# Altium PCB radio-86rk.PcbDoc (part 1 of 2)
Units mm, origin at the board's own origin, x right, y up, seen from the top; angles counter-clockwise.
Board outline 258 x 185 mm, 2 copper layers (Top Layer, Top, Bottom Layer, Bottom); 104 components, 185 nets, 870 pads, 319 vias.
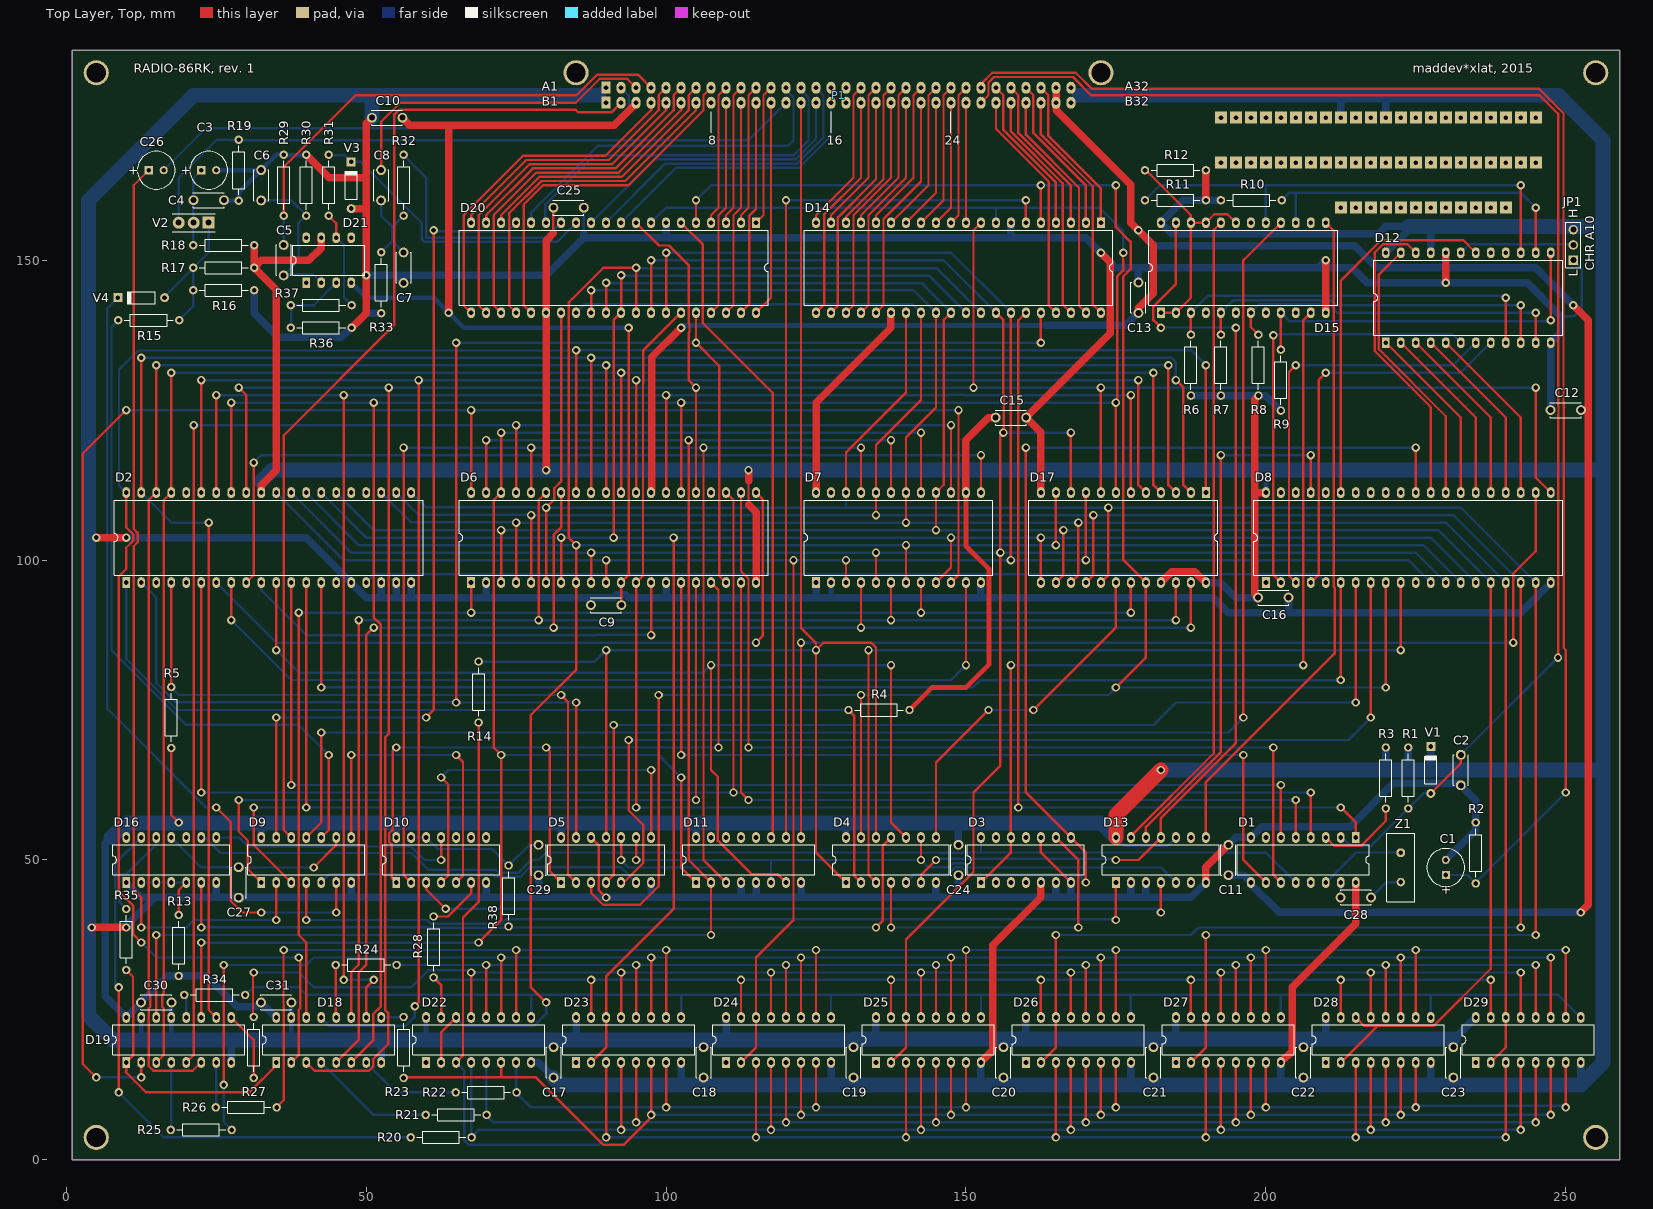
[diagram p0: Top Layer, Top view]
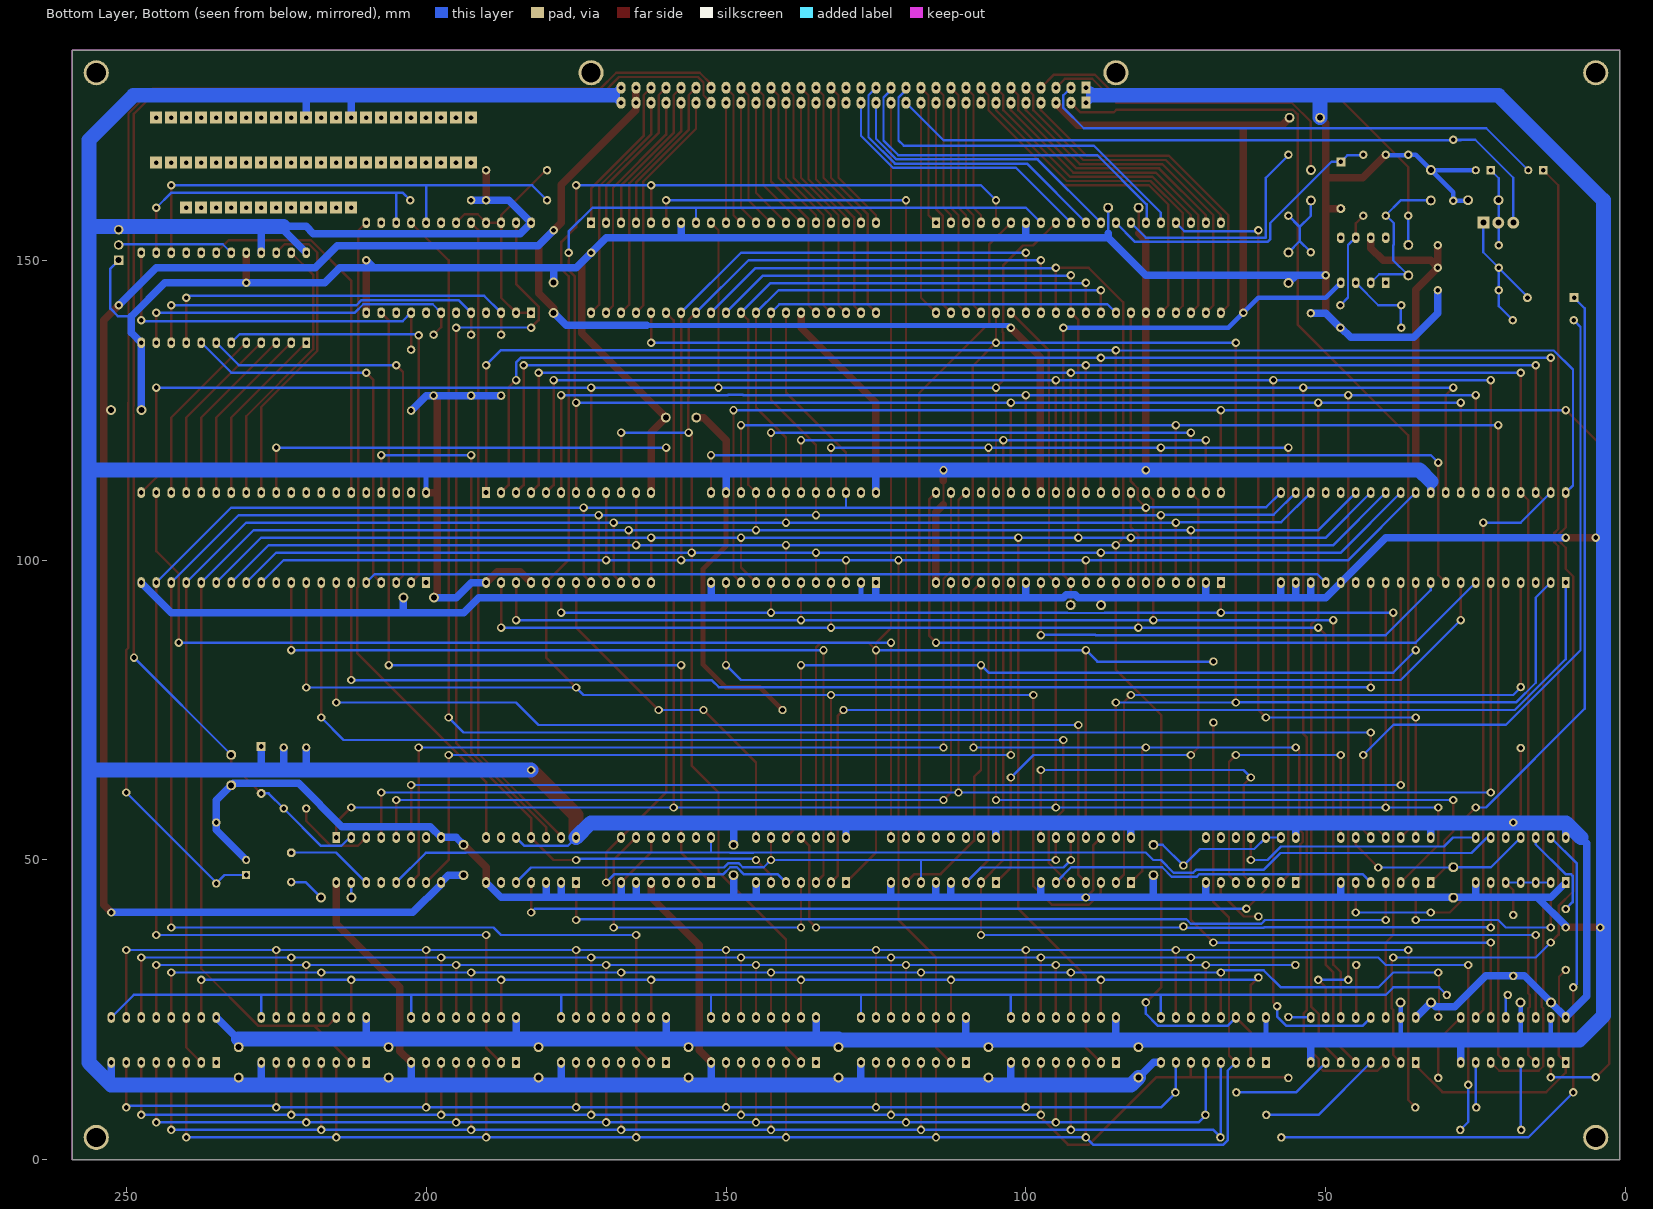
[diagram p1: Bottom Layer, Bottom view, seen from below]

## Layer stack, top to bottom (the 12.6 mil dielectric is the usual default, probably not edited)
Top Solder, Top Mask: solder mask 0.0102, Solder Resist, Dk 3.5
Top Layer, Top: signal copper 0.0356
Dielectric 1: dielectric 0.32, FR-4, Dk 4.8
Bottom Layer, Bottom: signal copper 0.0356
Bottom Solder, Bot Mask: solder mask 0.0102, Solder Resist, Dk 3.5

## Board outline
1,0 1,185 259,185 259,0

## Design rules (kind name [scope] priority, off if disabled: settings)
AssemblyTestPointUsage [All] p1 off:
AssemblyTestpoint [All] p1 off: testpointundercomponent=TRUE minsize=1.016 maxsize=2.54 preferedsize=1.524 minholesize=0 maxholesize=1.016 preferedholesize=0.813 testpointgrid=0.025 usegrid=TRUE gridtolerance=0 allowsidetop=TRUE allowsidebottom=TRUE
Clearance "PCB edge to copper" [OnLayer('Keep-Out Layer, Board') vs OnCopper] p1: gap=0.5
Clearance "Hole to copper" [InPadClass('Hole')] p2: gap=0.4
Clearance "VDD to free pad" [InNet('VDD') AND IsPad AND (Component = 'P1')] p3: gap=0.3
Clearance VDD [InNet('VDD')] p4: gap=0.5
Clearance [All] p5: gap=0.3
ComponentClearance ComponentClearance_1 [NAME LIKE 'C*'] p1: gap=0 collisioncheckmode=3 verticalgap=0.254 showdistances=FALSE
ComponentClearance [All] p2: gap=0.254 collisioncheckmode=3 verticalgap=0.254 showdistances=FALSE
FabricationTestPointUsage [All] p1 off: valid=0 allowmultiple=FALSE
FabricationTestpoint [All] p1 off: side=3 testpointundercomponent=TRUE minsize=1.016 maxsize=2.54 preferedsize=1.524 minholesize=0 maxholesize=1.016 preferedholesize=0.813 testpointgrid=0.025 allowsidetop=TRUE allowsidebottom=TRUE usegrid=TRUE gridtolerance=0
HoleSize [All] p1: absolutevalues=TRUE maxlimit=3.5 minlimit=0.4 maxpercent=80.000 minpercent=20.000
MinimumAnnularRing [All] p1: minimumring=0.25
PlaneClearance [All] p1: clearance=0.254
PolygonConnect PolygonConnect_2 [IsPolygon And InNet('NET 178') And OnLayer('Bottom Layer, Bottom') vs IsVia] p1: connectstyle=Direct reliefconductorwidth=0.33 reliefentries=4 polygonreliefangle="90 Angle" airgapwidth=0.254
PolygonConnect PolygonConnect_1 [IsPolygon And InNet('NET 178') And OnLayer('Bottom Layer, Bottom') vs IsPad] p2: connectstyle=Direct reliefconductorwidth=0.33 reliefentries=4 polygonreliefangle="90 Angle" airgapwidth=0.254
PolygonConnect [All] p3: connectstyle=Relief reliefconductorwidth=0.254 reliefentries=4 polygonreliefangle="90 Angle" airgapwidth=0.254
RoutingVias [All] p1: holewidth=0.8 width=1.4 viastyle="Through Hole" minholewidth=0.8 minwidth=1.4 maxholewidth=0.8 maxwidth=1.4
SilkToSolderMaskClearance "Text over via" [IsVia vs IsText] p1: minsilkscreentomaskgap=0.205 clearancetoexposedcopper=TRUE
SilkToSolderMaskClearance [IsPad] p2: minsilkscreentomaskgap=0.205 clearancetoexposedcopper=TRUE
SolderMaskExpansion [All] p1: expansion=0.11
Width [All] p1: maxlimit=3 minlimit=0.4 preferedwidth=0.4 minimp=50.000000 maximp=50.000000 favimp=50.000000
21 further rules are at their usual default settings.

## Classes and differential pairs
pad class Hole: Free-hole
component class radio-86rk_cpu_pio: C1 C2 C5 C6 C7 C8 C9 C10 C11 C12 C13 C15 C16 C17 C18 C19 C20 C21 C22 C23 C24 C25 C26 C28 C30 C31 D1 D6 D9 D14 D20 D21 P1 R1 R2 R3 R29 R30 R31 R32 R33 R36 R37 V1 V3 Z1
component class radio-86rk_control: C27 C29 D10 D11 D13 D16 D18 D19 R13 R14 R20 R21 R22 R23 R24 R25 R26 R27 R28 R34 R35 R38
component class radio-86rk_dma_crt: C3 C4 D2 D3 D4 D5 D7 D8 D12 D15 JP1 R4 R5 R6 R7 R8 R9 R10 R11 R12 R15 R16 R17 R18 R19 V2 V4
component class radio-86rk_rom_ram: D17 D22 D23 D24 D25 D26 D27 D28 D29

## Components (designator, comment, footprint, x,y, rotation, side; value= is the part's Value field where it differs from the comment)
C1 "4.7uF/6V" CAPPR2.5-6.3x11 230,48.75 r90 top
C2 "0.47 uF" CAPR5.08-5.1x2.5 232.5,65 r90 top
C3 "47uF/15V" CAPPR2.5-6.3x11 23.75,165 r0 top
C4 "0.1uF" CAPR5.08-5.1x2.5 23.75,160 r180 top
C5 "0.22uF" CAPR5.08-5.1x2.5 36.25,150 r90 top
C6 "2200pF" CAPR5.08-5.1x2.5 32.5,162.5 r270 top
C7 "0.1uF" CAPR5.08-5.1x2.5 56.25,148.75 r90 top
C8 "0.1uF" CAPR5.08-5.1x2.5 52.5,162.5 r270 top
C9 "0.1uF" CAPR5.08-5.1x2.5 90,92.5 r0 top
C10 "0.1uF" CAPR5.08-5.1x2.5 53.5,173.75 r0 top
C11 "0.1uF" CAPR5.08-5.1x2.5 193.75,50 r270 top
C12 "0.1uF" CAPR5.08-5.1x2.5 250,125 r0 top
C13 "0.1uF" CAPR5.08-5.1x2.5 178.75,143.75 r270 top
C15 "0.1uF" CAPR5.08-5.1x2.5 157.5,123.75 r180 top
C16 "0.1uF" CAPR5.08-5.1x2.5 201.25,93.75 r180 top
C17 "0.1uF" CAPR5.08-5.1x2.5 81.25,16.25 r270 top
C18 "0.1uF" CAPR5.08-5.1x2.5 106.25,16.25 r270 top
C19 "0.1uF" CAPR5.08-5.1x2.5 131.25,16.25 r270 top
C20 "0.1uF" CAPR5.08-5.1x2.5 156.25,16.25 r270 top
C21 "0.1uF" CAPR5.08-5.1x2.5 181.25,16.25 r270 top
C22 "0.1uF" CAPR5.08-5.1x2.5 206.25,16.25 r270 top
C23 "0.1uF" CAPR5.08-5.1x2.5 231.25,16.25 r270 top
C24 "0.1uF" CAPR5.08-5.1x2.5 148.75,50 r90 top
C25 "0.1uF" CAPR5.08-5.1x2.5 83.75,158.75 r180 top
C26 "10uF/6.3V" CAPPR2.5-6.3x11 15,165 r0 top
C27 "2200pF" CAPR5.08-5.1x2.5 28.75,46.25 r270 top
C28 "*" CAPR5.08-5.1x2.5 215,43.75 r0 top
C29 "300pF" CAPR5.08-5.1x2.5 78.75,50 r270 top
C30 "0.1uF" CAPR5.08-5.1x2.5 15,26.25 r180 top
C31 "0.1uF" CAPR5.08-5.1x2.5 35,26.25 r180 top
D1 "КР580ГФ24" DIP16M 206.25,50 r180 top
D2 "КР580ИК57" DIP40M 33.75,103.75 r0 top
D3 "К155ИЕ4" DIP14M 160,50 r0 top
D4 "К155ЛИ1" DIP14M 137.5,50 r0 top
D5 "К155ЛП5" DIP14M 90,50 r0 top
D6 "КР580ВМ80А" DIP40M 91.25,103.75 r0 top
D7 "КР589ИР12" DIP24M 138.75,103.75 r0 top
D8 "КР580ВГ75" DIP40M 223.75,103.75 r0 top
D9 "К155ЛН1" DIP14M 40,50 r0 top
D10 "К155ЛА3" DIP14M 62.5,50 r0 top
D11 "К155ИД7" DIP16M 113.75,50 r0 top
D12 "К573РФ2" DIP24M 233.75,143.75 r0 top
D13 "К155ТМ2" DIP14M 182.5,50 r0 top
D14 "КР580ИК55" DIP40M 148.75,148.75 r180 top
D15 "К155ИР13" DIP24M 196.25,148.75 r0 top
D16 "К155ИР1" DIP14M 17.5,50 r0 top
D17 "К573РФ2" DIP24M 176.25,103.75 r180 top
D18 "К555КП11" DIP16M 43.75,20 r0 top
D19 "К555КП11" DIP16M 18.75,20 r0 top
D20 "КР580ИК55" DIP40M 91.25,148.75 r180 top
D21 "К140УД608" DIP8M 43.75,150 r0 top
D22 "КР565РУ5" DIP16M 68.75,20 r0 top
D23 "КР565РУ5" DIP16M 93.75,20 r0 top
D24 "КР565РУ5" DIP16M 118.75,20 r0 top
D25 "КР565РУ5" DIP16M 143.75,20 r0 top
D26 "КР565РУ5" DIP16M 168.75,20 r0 top
D27 "КР565РУ5" DIP16M 193.75,20 r0 top
D28 "КР565РУ5" DIP16M 218.75,20 r0 top
D29 "КР565РУ5" DIP16M 243.75,20 r0 top
JP1 "PLS-3" HDR1X3 251.25,150 r90 top
P1 "СНП58-64/94x9В-23-2-В" snp58 90,178.75 r0 top
R1 "2K" AXIAL-0.4 223.75,63.67 r90 top
R2 "10K" AXIAL-0.4 235,51.17 r270 top
R3 "1K" AXIAL-0.4 220,63.67 r270 top
R4 "10K" AXIAL-0.4 135.5,75 r180 top
R5 "10K" AXIAL-0.4 17.5,73.75 r90 top
R6 "10K" AXIAL-0.4 187.5,132.5 r270 top
R7 "10K" AXIAL-0.4 192.5,132.5 r270 top
R8 "10K" AXIAL-0.4 198.75,132.5 r270 top
R9 "10K" AXIAL-0.4 202.5,130 r270 top
R10 "10K" AXIAL-0.4 197.58,160 r180 top
R11 "10K" AXIAL-0.4 184.92,160 r0 top
R12 "20K" AXIAL-0.4 184.92,165 r0 top
R13 "20K" AXIAL-0.4 18.75,35.75 r90 top
R14 "33" AXIAL-0.4 68.75,78 r90 top
R15 "2.2k" AXIAL-0.4 13.75,140 r0 top
R16 "1k" AXIAL-0.4 26.25,145 r180 top
R17 "2.2k" AXIAL-0.4 26.25,148.75 r0 top
R18 "56" AXIAL-0.4 26.25,152.5 r180 top
R19 "75" AXIAL-0.4 28.75,165 r90 top
R20 "33" AXIAL-0.4 62.5,3.75 r180 top
R21 "33" AXIAL-0.4 65,7.5 r180 top
R22 "33" AXIAL-0.4 70,11.25 r180 top
R23 "33" AXIAL-0.4 56.25,18.75 r90 top
R24 "33" AXIAL-0.4 50,32.5 r180 top
R25 "33" AXIAL-0.4 22.5,5 r180 top
R26 "33" AXIAL-0.4 30,8.75 r180 top
R27 "33" AXIAL-0.4 31.25,18.75 r270 top
R28 "33" AXIAL-0.4 61.25,35.5 r90 top
R29 "12K" AXIAL-0.4 36.25,162.5 r270 top
R30 "2.4K" AXIAL-0.4 40,162.5 r270 top
R31 "330" AXIAL-0.4 43.75,162.5 r90 top
R32 "1K" AXIAL-0.4 56.25,162.5 r270 top
R33 "1K" AXIAL-0.4 52.5,146.25 r90 top
R34 "33" AXIAL-0.4 24.75,27.5 r180 top
R35 "*" AXIAL-0.4 10,36.75 r90 top
R36 "1K" AXIAL-0.4 42.5,138.75 r0 top
R37 "7.5K" AXIAL-0.4 42.5,142.5 r180 top
R38 "430" AXIAL-0.4 73.75,44 r90 top
V1 "KD503A" DO-35A 227.5,65 r90 top
V2 "KT315" KT315 21.25,156.25 r180 top
V3 "KD503A" DO-35A 47.5,162.5 r90 top
V4 "KD503A" DO-35A 12.5,143.75 r180 top
Z1 "16 MHz" HC-49U 222.5,48.75 r270 top

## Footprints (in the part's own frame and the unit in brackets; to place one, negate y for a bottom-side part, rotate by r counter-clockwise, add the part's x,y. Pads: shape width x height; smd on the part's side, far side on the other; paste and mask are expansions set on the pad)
AXIAL-0.4 [mm] "Axial Device, Thru-Hole; 2 Leads; 0.4 in Pin Spacing"
  round 1.4 hole 0.8: 1(-5.08,0) 2(5.08,0)
  silkscreen extent -4.06,-1.02 4.06,1.02
CAPPR2.5-6.3x11 [mm] "Capacitor, Electrolytic, Radial; Body 6.3 x 11 mm (Dia.xH typ); Pin Spacing 2.5 mm (typ)"
  rect 1.35x1.35 hole 0.8: 1(-1.25,0)
  round 1.35 hole 0.8: 2(1.25,0)
  silkscreen extent -3.15,-3.15 3.15,3.15
CAPR5.08-5.1x2.5 [mm] "Capacitor, Ceramic, Thru-Hole, Dipped Radial; Body 5.1 x 2.5 mm (WxT) Pin Spacing 5.08 mm (typ)"
  round 1.65 hole 1: 1(-2.54,0) 2(2.54,0)
  silkscreen extent -2.55,-1.25 2.55,1.25
DIP8M [mm] "2.5mm grid"
  rect 1.3x1.8 hole 0.8: 1(-3.75,-3.75)
  rrect100% 1.3x1.8 hole 0.8: 2(-1.25,-3.75) 3(1.25,-3.75) 4(3.75,-3.75) 5(3.75,3.75) 6(1.25,3.75) 7(-1.25,3.75) 8(-3.75,3.75)
  silkscreen extent -6,-2.5 6,2.5
DIP14M [mm] "2.5mm grid"
  rect 1.3x1.8 hole 0.8: 1(-7.5,-3.75)
  rrect100% 1.3x1.8 hole 0.8: 2(-5,-3.75) 3(-2.5,-3.75) 4(0,-3.75) 5(2.5,-3.75) 6(5,-3.75) 7(7.5,-3.75) 8(7.5,3.75) 9(5,3.75) 10(2.5,3.75) 11(0,3.75) 12(-2.5,3.75) 13(-5,3.75) 14(-7.5,3.75)
  silkscreen extent -9.75,-2.5 9.75,2.5
DIP16M [mm] "2.5mm grid"
  rect 1.3x1.8 hole 0.8: 1(-8.75,-3.75)
  rrect100% 1.3x1.8 hole 0.8: 2(-6.25,-3.75) 3(-3.75,-3.75) 4(-1.25,-3.75) 5(1.25,-3.75) 6(3.75,-3.75) 7(6.25,-3.75) 8(8.75,-3.75) 9(8.75,3.75) 10(6.25,3.75) 11(3.75,3.75) 12(1.25,3.75) 13(-1.25,3.75) 14(-3.75,3.75) 15(-6.25,3.75) 16(-8.75,3.75)
  silkscreen extent -11,-2.5 11,2.5
DIP24M [mm] "2.5mm grid, 239.24-1, 239.24-2, 239.24-6, 239.24-7"
  rect 1.3x1.8 hole 0.8: 1(-13.75,-7.5)
  rrect100% 1.3x1.8 hole 0.8: 2(-11.25,-7.5) 3(-8.75,-7.5) 4(-6.25,-7.5) 5(-3.75,-7.5) 6(-1.25,-7.5) 7(1.25,-7.5) 8(3.75,-7.5) 9(6.25,-7.5) 10(8.75,-7.5) 11(11.25,-7.5) 12(13.75,-7.5) 13(13.75,7.5) 14(11.25,7.5) 15(8.75,7.5) 16(6.25,7.5) 17(3.75,7.5) 18(1.25,7.5) 19(-1.25,7.5) 20(-3.75,7.5) 21(-6.25,7.5) 22(-8.75,7.5) 23(-11.25,7.5) 24(-13.75,7.5)
  silkscreen extent -15.75,-6.25 15.75,6.25
DIP40M [mm] "2.5mm grid, 2123.40-1"
  rect 1.3x1.8 hole 0.8: 1(-23.75,-7.5)
  rrect100% 1.3x1.8 hole 0.8: 2(-21.25,-7.5) 3(-18.75,-7.5) 4(-16.25,-7.5) 5(-13.75,-7.5) 6(-11.25,-7.5) 7(-8.75,-7.5) 8(-6.25,-7.5) 9(-3.75,-7.5) 10(-1.25,-7.5) 11(1.25,-7.5) 12(3.75,-7.5) 13(6.25,-7.5) 14(8.75,-7.5) 15(11.25,-7.5) 16(13.75,-7.5) 17(16.25,-7.5) 18(18.75,-7.5) 19(21.25,-7.5) 20(23.75,-7.5) 21(23.75,7.5) 22(21.25,7.5) 23(18.75,7.5) 24(16.25,7.5) 25(13.75,7.5) 26(11.25,7.5) 27(8.75,7.5) 28(6.25,7.5) 29(3.75,7.5) 30(1.25,7.5) 31(-1.25,7.5) 32(-3.75,7.5) 33(-6.25,7.5) 34(-8.75,7.5) 35(-11.25,7.5) 36(-13.75,7.5) 37(-16.25,7.5) 38(-18.75,7.5) 39(-21.25,7.5) 40(-23.75,7.5)
  silkscreen extent -25.75,-6.25 25.75,6.25
DO-35A [mm] "Diode, Axial; Body 4.6 x 1.9 mm (LxDia. max), Lead Dia. 0.53 mm (max)"
  round 1.5 hole 0.8: 1(-3.9,0)
  rect 1.5x1.5 hole 0.8: 2(3.9,0)
  silkscreen extent -2.3,-1 2.4,1
HC-49U [mm] "Quartz Crystal, Thru-Hole; 2 Leads; Body 11.35 x 4.65 x 13.46 mm (LxWxH max)"
  oct 1.4x1.4 hole 0.8: 1(-2.44,0)
  round 1.4 hole 0.8: 2(2.44,0)
  silkscreen extent -5.7,-2.35 5.7,2.35
HDR1X3 [mm] "Connector; Header; 3 Position"
  rect 1.6x1.6 hole 1: 1(0,0)
  round 1.6 hole 1: 2(2.54,0) 3(5.08,0)
  silkscreen extent -1.27,-1.27 6.35,1.27
KT315 [mm]
  rect 2x2 hole 1: B(-2.5,0)
  round 2 hole 1: C(0,0) E(2.5,0)
  silkscreen extent -3.6,-1.5 3.6,1.5
snp58 [mm]
  rect 1.5x2 hole 0.8: A1(0,0) B1(0,-2.5)
  oval 1.5x2 hole 0.8: A2(2.5,0) A3(5,0) A4(7.5,0) A5(10,0) A6(12.5,0) A7(15,0) A8(17.5,0) A9(20,0) A10(22.5,0) A11(25,0) A12(27.5,0) A13(30,0) A14(32.5,0) A15(35,0) A16(37.5,0) A17(40,0) A18(42.5,0) A19(45,0) A20(47.5,0) A21(50,0) A22(52.5,0) A23(55,0) A24(57.5,0) A25(60,0) A26(62.5,0) A27(65,0) A28(67.5,0) A29(70,0) A30(72.5,0) A31(75,0) A32(77.5,0) B2(2.5,-2.5) B3(5,-2.5) B4(7.5,-2.5) B5(10,-2.5) B6(12.5,-2.5) B7(15,-2.5) B8(17.5,-2.5) B9(20,-2.5) B10(22.5,-2.5) B11(25,-2.5) B12(27.5,-2.5) B13(30,-2.5) B14(32.5,-2.5) B15(35,-2.5) B16(37.5,-2.5) B17(40,-2.5) B18(42.5,-2.5) B19(45,-2.5) B20(47.5,-2.5) B21(50,-2.5) B22(52.5,-2.5) B23(55,-2.5) B24(57.5,-2.5) B25(60,-2.5) B26(62.5,-2.5) B27(65,-2.5) B28(67.5,-2.5) B29(70,-2.5) B30(72.5,-2.5) B31(75,-2.5) B32(77.5,-2.5)

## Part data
C1 C3 C26: library part "Cap Pol2", "Polarized Capacitor (Axial)"
C2 C4 C5 C6 C7 C8 C9 C10 C11 C12 C13 C15 C16 C17 C18 C19 C20 C21 C22 C23 C24 C25 C27 C28 C29 C30 C31: library part Cap, "Capacitor"
D1: "Clock generator and driver for 8080A CPU"
D2: "Programmable DMA controller"
D3: library part SN7492AN, "Divide-by-Twelve Counter"
D4: library part SN7408N, "Quadruple 2-Input Positive-AND Gate"
D5: library part SN7486N, "Quadruple 2-Input Exclusive-OR Gate"
D6: "8-bit N-channel microprocessor"
D7: library part 8212, "8-bit input/output port"
D8: "Programmable CRT controller"
D9: library part SN7404N, "Hex Inverter"
D10: library part SN7400N, "Quadruple 2-Input Positive-NAND Gate"
D11: library part SN74LS138N, "3-Line to 8-Line Decoder / Demultiplexer"
D13: library part SN7474N, "Dual D-Type Positive-Edge-Triggered Flip-Flop with Preset and Clear"
D14 D20: "Programmable peripheral interface"
D15: library part SN74198N, "8-Bit Shift Register"
D16: library part SN7495AN, "4-Bit Parallel-Access Shift Register"
D18 D19: library part SN74LS257BN, "Quadruple 2-Line to 1-Line Data Selector/Multiplexer with 3-State Outputs"
D21: library part MC1456P1, "High-Performance Operational Amplifier"
D22 D23 D24 D25 D26 D27 D28 D29: library part 4164, "64K X 1 bit dynamic RAM"
JP1: library part "Header 3", "Header, 3-Pin"
R1 R2 R3 R4 R5 R6 R7 R8 R9 R10 R11 R12 R13 R14 R15 R16 R17 R18 R19 R20 R21 R22 R23 R24 R25 R26 R27 R28 R29 R30 R31 R32 R33 R34 R35 R36 R37 R38: library part Res2, "Resistor"
V1 V3 V4: library part "Diode 1N4149", "Computer Diode"
V2: library part NPN, "NPN Bipolar Transistor"
Z1: library part XTAL, "Crystal Oscillator"

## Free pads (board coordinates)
  rect 2x2 hole 0.8: 0(192.5,166.25) 0(192.5,173.75) 0(195,166.25) 0(195,173.75) 0(197.5,166.25) 0(197.5,173.75) 0(200,166.25) 0(200,173.75) 0(202.5,166.25) 0(202.5,173.75) 0(205,166.25) 0(205,173.75) 0(207.5,166.25) 0(207.5,173.75) 0(210,166.25) 0(210,173.75) 0(212.5,158.75) 0(212.5,166.25) 0(212.5,173.75) 0(215,158.75) 0(215,166.25) 0(215,173.75) 0(217.5,158.75) 0(217.5,166.25) 0(217.5,173.75) 0(220,158.75) 0(220,166.25) 0(220,173.75) 0(222.5,158.75) 0(222.5,166.25) 0(222.5,173.75) 0(225,158.75) 0(225,166.25) 0(225,173.75) 0(227.5,158.75) 0(227.5,166.25) 0(227.5,173.75) 0(230,158.75) 0(230,166.25) 0(230,173.75) 0(232.5,158.75) 0(232.5,166.25) 0(232.5,173.75) 0(235,158.75) 0(235,166.25) 0(235,173.75) 0(237.5,158.75) 0(237.5,166.25) 0(237.5,173.75) 0(240,158.75) 0(240,166.25) 0(240,173.75) 0(242.5,166.25) 0(242.5,173.75) 0(245,166.25) 0(245,173.75)
  round 4.2 hole 3.2: hole(5,181.25) hole(5,3.75) hole(85,181.25) hole(172.5,181.25) hole(255,181.25) hole(255,3.75)

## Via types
v1: diameter 1.4, hole 0.8, Top Layer, Top to Bottom Layer, Bottom, 318 vias
v2: diameter 1.4, hole 0.8, Top Layer, Top to Bottom Layer, Bottom, tented both sides, 1 vias

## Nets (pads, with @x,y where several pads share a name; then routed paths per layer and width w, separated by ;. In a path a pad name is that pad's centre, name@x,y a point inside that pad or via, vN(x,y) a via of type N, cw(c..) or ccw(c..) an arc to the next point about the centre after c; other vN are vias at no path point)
A0: D2.32 D6.25 D8.21 D14.9 D17.8 D18.3 D20.9 | length 475.2
  Top Layer, Top w0.4: v1(28.75,128.75) 30,127.5 D2.32@30,111.25 ; D18.3@40,16.25 41.4,14.85 50.476,14.85 51.15,15.524 51.15,16.776 53.65,19.276 53.65,24.476 53.15,24.976 53.15,70.4 53.75,71 v1(53.75,128.75) ; D20.9@95,156.25 98.8,152.45 100.497,152.45 103.75,149.197 103.75,139.48 103.9,139.33 103.9,138.02 103.8,137.92 103.8,129.95 v1(105,128.75) D6.25@105,111.25 ; v1(151.25,128.75) 151.25,155 D14.9@152.5,156.25 ; D17.8@172.5,111.25 v1(172.5,128.75) ; v1(245,128.75) 245,113.75 D8.21@247.5,111.25
  Bottom Layer, Bottom w0.4: v1(28.75,128.75) v1(53.75,128.75) ; v1@53.75,128.7 v1@104.95,128.7 ; v1(105,128.75) v1(151.25,128.75) v1(172.5,128.75) v1(245,128.75)
A1: D2.33 D6.26 D14.8 D17.7 D18.6 D20.8 | length 418
  Top Layer, Top w0.4: D2.33@27.5,111.25 v1(27.5,126.25) ; D18.6@47.5,16.25 51.15,19.9 51.15,24.276 52.45,25.576 52.45,89.247 51.25,90.447 v1(51.25,126.25) ; D6.26@102.5,111.25 v1(102.5,126.25) ; D17.7@175,111.25 v1(175,126.25) 175.2,126.45 175.2,147.253 176.2,148.253 176.2,149.975 176.175,150 176.175,151.175 v1(176.25,151.25)
  Bottom Layer, Bottom w0.4: v1(27.5,126.25) 27.55,126.2 v1@51.2,126.2 ; v1(51.25,126.25) v1(102.5,126.25) v1(175,126.25) ; D20.8@97.5,156.25 100,158.75 172.257,158.75 176.25,154.757 v1(176.25,151.25) ; D14.8@155,156.25 155,158.749
A2: D2.34 D6.27 D17.6 D18.10 | length 310.6
  Top Layer, Top w0.4: D2.34@25,111.25 v1(25,127.5) ; v1(46.25,30) 46.25,98.125 v1(46.25,127.5) ; D18.10@50,23.75 50,28.75 v1(51.25,30) ; D6.27@100,111.25 100,112.5 v1(100,127.5) ; D17.6@177.5,111.25 v1(177.5,127.5)
  Bottom Layer, Bottom w0.4: v1(25,127.5) v1(46.25,127.5) v1(100,127.5) 147.133,127.5 147.207,127.574 149.662,127.574 149.736,127.5 v1(177.5,127.5) ; v1(46.25,30) v1(51.25,30)
A3: D2.35 D6.29 D17.5 D18.13 | length 336.2
  Top Layer, Top w0.4: D2.35@22.5,111.25 v1(22.5,130) ; v1(58.125,25.625) 58.75,26.25 v1(58.75,130) ; D6.29@95,111.25 v1(95,130) ; v1(178.75,130) 178.75,112.5 D17.5@180,111.25
  Bottom Layer, Bottom w0.4: v1(22.5,130) v1(58.75,130) v1(95,130) v1(178.75,130) ; D18.13@42.5,23.75 43.9,22.35 56.547,22.35 58.125,23.928 v1(58.125,25.625)
A4: D2.37 D6.30 D17.4 D19.3 | length 320.5
  Top Layer, Top w0.4: D19.3@15,16.25 16.25,17.5 16.25,25.25 16,25.5 16,27.5 16.25,27.75 16.25,110 D2.37@17.5,111.25 v1(17.5,131.25) ; D6.30@92.5,111.25 v1(92.5,131.25) ; v1(181.25,131.25) 181.25,112.5 D17.4@182.5,111.25
  Bottom Layer, Bottom w0.4: v1(17.5,131.25) v1(92.5,131.25) v1(181.25,131.25)
A5: D2.38 D6.31 D17.3 D19.6 | length 339
  Top Layer, Top w0.4: v1(15,132.5) D2.38@15,111.25 13.75,110 13.75,27.75 14,27.5 14,25.5 13.75,25.25 13.75,15.624 14.524,14.85 21.1,14.85 D19.6@22.5,16.25 ; D6.31@90,111.25 v1(90,132.5) ; v1(183.75,132.5) 183.75,112.5 D17.3@185,111.25
  Bottom Layer, Bottom w0.4: v1(15,132.5) v1(90,132.5) v1(183.75,132.5)
A6: D2.39 D6.32 D17.2 D19.10 | length 336.9
  Top Layer, Top w0.4: D2.39@12.5,111.25 v1(12.5,133.75) ; v1(23.75,106.25) 23.75,25 D19.10@25,23.75 ; D6.32@87.5,111.25 v1(87.5,133.75) ; v1(185,130) 186.25,128.75 186.25,112.5 D17.2@187.5,111.25
  Bottom Layer, Bottom w0.4: D2.39@12.5,111.25 17.5,106.25 v1(23.75,106.25) ; v1(12.5,133.75) v1(87.5,133.75) 184.197,133.75 185,132.947 v1(185,130)
A7: D2.40 D6.33 D17.1 D18.2 | length 373.2
  Top Layer, Top w0.4: D2.40@10,111.25 10,105.447 11.2,104.247 11.2,103.253 10,102.053 10,98.507 8.75,97.257 8.75,44.777 11.2,42.327 11.2,37.55 v1(12.5,36.25) ; D18.2@37.5,16.25 38.75,17.5 38.75,25 39,25.25 39,33.5 v1(38.75,33.75) ; D6.33@85,111.25 v1(85,135) ; D17.1@190,111.25 v1(190,132.5)
  Bottom Layer, Bottom w0.4: D2.40@10,111.25 8.8,112.45 8.8,131.747 12.003,134.95 84.95,134.95 v1(85,135) 187.5,135 v1(190,132.5) ; v1(12.5,36.25) 15,33.75 v1(38.75,33.75)
A8: D6.34 D7.4 D17.23 D18.5 | length 249.4
  Top Layer, Top w0.4: D18.5@45,16.25 48.75,20 48.75,31.25 50,32.5 50,87.5 v1(51.25,88.75) ; v1(81.25,88.75) 81.3,88.8 81.3,104.247 82.5,105.447 D6.34@82.5,111.25 ; v1(132.5,88.75) D7.4@132.5,96.25 ; v1(187.5,88.75) D17.23@187.5,96.25
  Bottom Layer, Bottom w0.4: v1(51.25,88.75) v1(81.25,88.75) v1(132.5,88.75) v1(187.5,88.75)
A9: D6.35 D7.6 D17.22 D18.11 | length 237.3
  Top Layer, Top w0.4: D18.11@47.5,23.75 47.5,31.273 48.75,32.523 v1(48.75,90) ; v1(78.75,90) 78.8,90.05 78.8,110.05 D6.35@80,111.25 ; v1(137.5,90) D7.6@137.5,96.25 ; v1(185,90) D17.22@185,96.25
  Bottom Layer, Bottom w0.4: v1(48.75,90) v1(78.75,90) v1(137.5,90) v1(185,90)
A10: D6.1 D7.8 D17.19 D18.14 | length 221.8
  Top Layer, Top w0.4: v1(38.75,91.25) 38.75,37.5 40,36.25 D18.14@40,23.75 ; v1(67.5,91.25) D6.1@67.5,96.25 ; v1(142.5,91.25) D7.8@142.5,96.25 ; v1(177.5,91.25) D17.19@177.5,96.25
  Bottom Layer, Bottom w0.4: v1(38.75,91.25) v1(67.5,91.25) 86.836,91.25 86.911,91.175 93.089,91.175 93.164,91.25 v1(142.5,91.25) v1(177.5,91.25)
A11: D6.40 D7.10 D19.2 | length 307
  Top Layer, Top w0.4: v1(5,13.75) 2.75,16 2.75,117.75 v1(10,125) ; v1(12.5,13.75) D19.2@12.5,16.25 ; D6.40@67.5,111.25 v2(67.5,125) ; D7.10@147.5,96.25 148.75,97.5 v1(148.75,125)
  Bottom Layer, Bottom w0.4: v1(5,13.75) v1(12.5,13.75) ; v1(10,125) v2(67.5,125) v1(148.75,125)
A12: D6.37 D7.15 D19.5 | length 255.5
  Top Layer, Top w0.4: D19.5@20,16.25 21.25,17.5 v1(21.25,122.5) ; D6.37@75,111.25 v1(75,122.5) ; D7.15@147.5,111.25 v1(147.5,122.5)
  Bottom Layer, Bottom w0.4: v1(21.25,122.5) v1(75,122.5) v1(147.5,122.5)
A13: D6.38 D7.17 D11.1 D19.11 | length 276.2
  Top Layer, Top w0.4: D19.11@22.5,23.75 v1(22.5,36.25) ; v1(68.75,36.25) 72.5,40 v1(72.5,67.5) 71.3,68.7 71.3,110.05 D6.38@72.5,111.25 v1(72.5,121.25) ; v1(102.5,63.75) 102.5,48.75 D11.1@105,46.25 ; D7.17@142.5,111.25 v1(142.5,121.25)
  Bottom Layer, Bottom w0.4: v1@22.7,36.2 37.972,36.2 37.999,36.174 68.674,36.174 v1(68.75,36.25) ; v1(72.5,67.5) 98.75,67.5 v1(102.5,63.75) ; v1(72.5,121.25) v1(142.5,121.25)
A14: D6.39 D7.19 D11.2 D19.14 | length 275.3
  Top Layer, Top w0.4: D19.14@15,23.75 v1(15,37.5) ; D6.39@70,111.25 v1(70,120) ; v1(103.75,120) 103.75,95 103.8,94.95 103.8,49.95 D11.2@107.5,46.25 v1(107.5,37.5) ; D7.19@137.5,111.25 v1(137.5,120)
  Bottom Layer, Bottom w0.4: v1(15,37.5) v1(107.5,37.5) ; v1(70,120) v1(103.75,120) v1(137.5,120)
A15: D5.10 D6.36 D7.21 D10.2 D11.3 | length 261.1
  Top Layer, Top w0.4: v1(56.25,118.75) 56.25,109.375 56.25,47.5 D10.2@57.5,46.25 ; D6.36@77.5,111.25 v1(77.5,118.75) ; v1(92.5,50) D5.10@92.5,53.75 ; v1(106.25,118.75) 106.25,50 D11.3@110,46.25 ; D7.21@132.5,111.25 v1(132.5,118.75)
  Bottom Layer, Bottom w0.4: v1(56.25,118.75) v1(77.5,118.75) v1(106.25,118.75) v1(132.5,118.75) ; v1(92.5,50) 93.75,48.75 107.5,48.75 D11.3@110,46.25
ATAPI: C5.2 P1.A4 R29.2 | length 81.5
  Top Layer, Top w0.4: R29.2@36.25,157.5 36.25,165.527 48.223,177.5 85.068,177.5 88.518,180.95 95.3,180.95 P1.A4@97.5,178.75
  Bottom Layer, Bottom w0.4: C5.2@36.25,152.54 R29.2@36.25,157.5
ATAPO: C8.1 P1.A3 | length 54.1
  Top Layer, Top w0.4: C8.1@52.5,165.04 52.5,173.074 55.676,176.25 84.943,176.25 88.943,180.25 93.5,180.25 P1.A3@95,178.75
B\W\R\: D4.1 D4.12 D5.11 P1.B14 R14.2 | length 263.9
  Top Layer, Top w0.4: D5.11@90,53.75 v1(90,85) ; P1.B14@122.5,176.25 122.5,88.65 125,86.15 v1(125,85) ; D4.1@130,46.25 125,51.25 v1(125,85) ; D4.12@135,53.75 135,85.447 134.247,86.2 126.2,86.2 v1(125,85)
  Bottom Layer, Bottom w0.4: R14.2@68.75,83.08 88.08,83.08 v1(90,85) v1(125,85)
BEEP: D6.16 D9.1 | length 127.8
  Top Layer, Top w0.4: v1(28.75,60) 28.75,54.75 30.25,53.25 30.25,48.5 D9.1@32.5,46.25 ; v1(105,60) D6.16@105,96.25
  Bottom Layer, Bottom w0.4: v1(28.75,60) v1(105,60)
BUZ: C26.2 P1.A2 | length 85.7
  Bottom Layer, Bottom w0.4: C26.2@16.25,165 23.25,172 90.368,172 93.75,175.382 93.75,177.5 P1.A2@92.5,178.75
C\A\S\: D22.15 D23.15 D24.15 D25.15 D26.15 D27.15 D28.15 D29.15 R28.1 | length 227.4
  Top Layer, Top w0.4: R28.1@61.25,30.42 62.5,29.17 D22.15@62.5,23.75 ; D23.15@87.5,23.75 v1(87.5,30) ; D24.15@112.5,23.75 v1(112.5,30) ; D25.15@137.5,23.75 v1(137.5,30) ; D26.15@162.5,23.75 v1(162.5,30) ; D27.15@187.5,23.75 v1(187.5,30) ; D28.15@212.5,23.75 v1(212.5,30) ; D29.15@237.5,23.75 v1(237.5,30)
  Bottom Layer, Bottom w0.4: R28.1@61.25,30.42 61.67,30 v1(87.5,30) v1(112.5,30) v1(137.5,30) v1(162.5,30) v1(187.5,30) v1(212.5,30) v1(237.5,30)
C\S\C\R\T\: D8.22 D11.9 | length 177.8
  Top Layer, Top w0.4: D11.9@122.5,53.75 v1(122.5,86.25) ; v1(241.25,86.25) 241.25,97.75 245,101.5 D8.22@245,111.25
  Bottom Layer, Bottom w0.4: v1(122.5,86.25) v1(241.25,86.25)
C\S\D\M\A\: D2.11 D4.10 D11.7 | length 189.6
  Top Layer, Top w0.4: v1(35,85) D2.11@35,96.25 ; v1(107.5,82.5) 107.5,65.023 108.65,63.873 108.65,53.224 114.224,47.65 118.6,47.65 D11.7@120,46.25 ; v1(137.5,82.5) 137.5,56.25 D4.10@140,53.75
  Bottom Layer, Bottom w0.4: v1(35,85) 38.75,81.25 106.25,81.25 v1(107.5,82.5) v1(137.5,82.5)
C\S\P\P\I\0\: D11.11 D20.6 | length 108.9
  Top Layer, Top w0.4: D20.6@102.5,156.25 106.15,152.6 106.15,139.475 117.775,127.85 117.775,54.025 D11.11@117.5,53.75
C\S\P\P\I\1\: D11.10 D14.6 | length 150
  Top Layer, Top w0.4: D11.10@120,53.75 120,103.75 v1(120,160) ; D14.6@160,156.25 v1(160,160)
  Bottom Layer, Bottom w0.4: v1(120,160) v1(160,160)
C\S\R\O\M\: D4.8 D17.18 | length 59.3
  Top Layer, Top w0.4: D4.8@145,53.75 145,66.25 v1(153.75,75) ; v1(161.25,75) 175,88.75 D17.18@175,96.25
  Bottom Layer, Bottom w0.4: v1(153.75,75) v1(161.25,75)
CHR_A10: D12.19 JP1.2 | length 19.4
  Bottom Layer, Bottom w0.4: D12.19@232.5,151.25 233.9,152.65 251.1,152.65 JP1.2@251.25,152.5
CLK: D1.6 D2.12 | length 207.5
  Top Layer, Top w0.4: v1(37.5,62.5) D2.12@37.5,96.25 ; D1.6@202.5,53.75 v1(202.5,62.5)
  Bottom Layer, Bottom w0.4: v1(37.5,62.5) v1(202.5,62.5)
D0: D2.30 D6.10 D7.3 D8.12 D14.34 D17.9 D20.34 D24.2 D24.14 | length 417.8
  Top Layer, Top w0.4: D6.10@90,96.25 v1(90,100) ; D20.34@100,141.25 v1(100,151.25) ; D24.2@112.5,16.25 115,18.75 D24.14@115,23.75 115,33.75 121.25,40 v1(121.25,100) ; D7.3@130,96.25 v1(130,100) ; v1(157.5,100) D14.34@157.5,141.25 ; v1(170,100) D17.9@170,111.25
  Bottom Layer, Bottom w0.4: D2.30@35,111.25 46.3,99.95 89.95,99.95 v1(90,100) v1(121.25,100) v1(130,100) v1(157.5,100) v1(170,100) 223.75,100 D8.12@227.5,96.25 ; v1(100,151.25) 147.5,151.25 D14.34@157.5,141.25
D1: D2.29 D6.9 D7.5 D8.13 D14.33 D17.10 D20.33 D25.2 D25.14 | length 433.2
  Top Layer, Top w0.4: D6.9@87.5,96.25 v1(87.5,101.25) ; D20.33@97.5,141.25 v1(97.5,150) ; D7.5@135,96.25 v1(135,101.25) ; D25.2@137.5,16.25 140,18.75 D25.14@140,23.75 140,36.75 151.25,48 151.25,61.25 155.75,65.75 v1(155.75,101.25) 155.75,120.75 v1(156.25,121.25) 156.285,121.285 156.285,127.132 156.25,127.167 156.25,140 D14.33@155,141.25 ; D17.10@167.5,111.25 v1(167.5,121.25)
  Bottom Layer, Bottom w0.4: D2.29@37.5,111.25 47.55,101.2 87.45,101.2 v1(87.5,101.25) v1(135,101.25) v1(155.75,101.25) 225,101.25 D8.13@230,96.25 ; v1(97.5,150) 146.25,150 D14.33@155,141.25 ; v1(156.25,121.25) v1(167.5,121.25)
D2: D2.28 D6.8 D7.7 D8.14 D14.32 D17.11 D20.32 D22.2 D22.14 | length 443.7
  Top Layer, Top w0.4: D22.2@62.5,16.25 62.5,21.25 D22.14@65,23.75 ; v1(80,26.25) 77.425,28.825 77.425,74.122 85,81.697 D6.8@85,96.25 v1(85,102.5) 83.8,103.7 83.8,142.997 89.553,148.75 v1(95,148.75) D20.32@95,141.25 ; D7.7@140,96.25 v1(140,102.5) ; v1(165,102.5) D17.11@165,111.25
  Bottom Layer, Bottom w0.4: D2.28@40,111.25 48.8,102.45 84.95,102.45 v1(85,102.5) v1(140,102.5) v1(165,102.5) 226.25,102.5 D8.14@232.5,96.25 ; D22.14@65,23.75 66.4,22.35 77.976,22.35 80,24.374 v1(80,26.25) ; v1(95,148.75) 95.076,148.674 145.076,148.674 D14.32@152.5,141.25
D3: D2.27 D6.7 D7.9 D8.15 D14.31 D17.13 D20.31 D23.2 D23.14 | length 419.8
  Top Layer, Top w0.4: D6.7@82.5,96.25 v1(82.5,103.75) ; D23.2@87.5,16.25 90,18.75 D23.14@90,23.75 90,30.602 101.25,41.852 v1(101.25,103.75) ; v1(91.25,103.75) 91.25,140 D20.31@92.5,141.25 v1(92.5,147.5) ; D7.9@145,96.25 147.5,98.75 v1(147.5,103.75) ; D17.13@162.5,96.25 v1(162.5,103.75)
  Bottom Layer, Bottom w0.4: D2.27@42.5,111.25 50.05,103.7 v1@82.45,103.7 ; v1(82.5,103.75) v1(91.25,103.75) v1(101.25,103.75) v1(147.5,103.75) v1(162.5,103.75) 227.5,103.75 D8.15@235,96.25 ; v1(92.5,147.5) 92.576,147.424 143.826,147.424 D14.31@150,141.25
D4: D2.26 D6.3 D7.16 D8.16 D14.30 D17.14 D20.30 D28.2 D28.14 | length 418.6
  Top Layer, Top w0.4: D6.3@72.5,96.25 v1(72.5,105) ; D20.30@90,141.25 v1(90,146.25) ; v1(145,105) D7.16@145,111.25 146.3,112.55 146.3,140.05 D14.30@147.5,141.25 ; D17.14@165,96.25 166.25,97.5 v1(166.25,105) ; D28.2@212.5,16.25 218.6,22.35 ; D28.14@215,23.75 216.4,22.35 218.6,22.35 ; D8.16@237.5,96.25 237.5,31.874 227.976,22.35 218.6,22.35
  Bottom Layer, Bottom w0.4: D2.26@45,111.25 51.25,105 v1(72.5,105) v1(145,105) v1(166.25,105) 228.75,105 D8.16@237.5,96.25 ; v1(90,146.25) 90.076,146.174 142.576,146.174 D14.30@147.5,141.25
D5: D2.23 D6.4 D7.18 D8.17 D14.29 D17.15 D20.29 D29.2 D29.14 | length 395.1
  Top Layer, Top w0.4: D6.4@75,96.25 v1(75,106.25) ; D20.29@87.5,141.25 v1(87.5,145) ; v1(140,106.25) D7.18@140,111.25 140,120.447 145,125.447 D14.29@145,141.25 ; D17.15@167.5,96.25 168.75,97.5 v1(168.75,106.25) ; D29.2@237.5,16.25 240,18.75 D29.14@240,23.75 D8.17@240,96.25
  Bottom Layer, Bottom w0.4: D2.23@52.5,111.25 57.45,106.3 v1@74.95,106.3 ; v1(75,106.25) v1(140,106.25) v1(168.75,106.25) 230,106.25 D8.17@240,96.25 ; v1(87.5,145) 141.25,145 D14.29@145,141.25
D6: D2.22 D6.5 D7.20 D8.18 D14.28 D17.16 D20.28 D26.2 D26.14 | length 470
  Top Layer, Top w0.4: D6.5@77.5,96.25 v1(77.5,107.5) ; v1(135,107.5) D7.20@135,111.25 135,119.197 142.5,126.697 D14.28@142.5,141.25 ; D26.2@162.5,16.25 165,18.75 D26.14@165,23.75 v1(165,37.5) ; D17.16@170,96.25 171.25,97.5 v1(171.25,107.5) ; v1(242.5,38.75) D8.18@242.5,96.25
  Bottom Layer, Bottom w0.4: D2.22@55,111.25 58.7,107.55 v1@77.45,107.55 ; v1(77.5,107.5) v1(135,107.5) v1(171.25,107.5) 231.25,107.5 D8.18@242.5,96.25 ; D20.28@85,141.25 86.4,142.65 141.1,142.65 D14.28@142.5,141.25 ; v1(165,37.5) 187.5,37.5 188.75,38.75 v1(242.5,38.75)
D7: D2.21 D6.6 D7.22 D8.19 D14.27 D17.17 D20.27 D27.2 D27.14 | length 425.4
  Top Layer, Top w0.4: D6.6@80,96.25 v1(80,108.75) 81.35,110.1 81.35,111.976 82.5,113.126 82.5,116.75 D20.27@82.5,141.25 ; D7.22@130,111.25 130,117.947 140,127.947 D14.27@140,141.25 ; D17.17@172.5,96.25 173.75,97.5 v1(173.75,108.75) ; D27.2@187.5,16.25 190,18.75 D27.14@190,23.75 v1(190,37.5) ; v1(245,37.5) D8.19@245,96.25
  Bottom Layer, Bottom w0.4: D2.21@57.5,111.25 59.95,108.8 v1@79.95,108.8 ; v1(80,108.75) 130,108.75 ; D7.22@130,111.25 130,108.75 ; v1(190,37.5) v1(245,37.5) ; D8.19@245,96.25 232.5,108.75 v1(173.75,108.75) 130,108.75
DBIN: D5.1 D6.17 D10.1 | length 128.8
  Top Layer, Top w0.4: D10.1@55,46.25 54.25,47 54.25,52.624 53.85,53.024 53.85,54.476 54.45,55.076 54.45,68.2 v1(55,68.75) ; v1(80,68.75) 80.625,68.125 80.625,48.125 D5.1@82.5,46.25 ; D6.17@107.5,96.25 108.75,95 v1(108.75,68.75)
  Bottom Layer, Bottom w0.4: v1(55,68.75) v1(80,68.75) v1(108.75,68.75)
GND: C1.2 C2.1 C3.2 C4.1 C6.1 C7.1 C9.1 C10.1 C11.1 C12.1 C13.1 C15.1 C16.1 C17.1 C18.1 C19.1 C20.1 C21.1 C22.1 C23.1 C24.1 C25.1 C27.2 C29.2 C30.1 C31.1 D1.8 D2.16 D2.18 D2.19 D2.20 D3.6 D3.7 D3.10 D4.7 D5.7 D5.12 D6.2 D6.14 D7.1 D7.2 D7.12 D8.20 D9.7 D10.7 D11.4 D11.5 D11.8 D12.12 D12.20 D13.2 D13.3 D13.7 D14.7 D15.12 D16.1 D16.7 D17.12 D18.8 D18.15 D19.8 D19.13 D19.15 D20.7 D22.16 D23.16 D24.16 D25.16 D26.16 D27.16 D28.16 D29.16 JP1.1 P1.A1 P1.B1 R2.1 R16.1 R19.1 R29.1 R30.1 R33.1 R36.2 V3.1 | length 1535.3
  Top Layer, Top w0.4: D5.12@87.5,53.75 88.75,52.5 88.75,44.996 v1(89.997,43.749) ; D3.10@162.5,53.75 162.5,51.25 D3.7@167.5,46.25
  Top Layer, Top w1.25: v1(4.25,38.75) v1(10,38.75) ; v1(5,103.75) v1(10,103.75) ; R30.1@40,167.58 43.83,163.75 50,163.75 ; R36.2@47.5,138.75 R36.2@47.54,138.79 ; V3.1@47.5,158.6 49.85,158.6 ; R36.2@47.58,138.75 50,141.17 v1(50,147.5) 50,163.75 ; C10.1@50.96,173.75 50,172.79 50,163.75 ; C15.1@160.04,123.75 162.5,121.29 D17.12@162.5,111.25 ; C15.1@160.04,123.79 174.075,137.825 174.075,149.675 v1(172.5,151.25) ; D13.7@190,46.25 190,48.79 C11.1@193.75,52.54 ; D15.12@210,141.25 v1(210,150) ; v1(230,146.25) D12.20@230,151.25
  Bottom Layer, Bottom w0.4: 86.25,154.5 86.25,158.71 C25.1@86.29,158.75 ; C9.1@87.46,92.5 87.5,92.54 87.5,93.749 ; 249.125,140.673 251.403,140.673 252.65,141.92 252.65,148.6 JP1.1@251.25,150
  Bottom Layer, Bottom w0.8: D19.15@12.5,23.75 12.5,20.109 12.61,19.999 ; 17.5,19.999 D19.13@17.5,23.75 17.5,26.21 C30.1@17.54,26.25 ; C3.2@25,165 C6.1@32.46,165 ; C4.1@26.29,160 26.37,159.92 R19.1@28.75,159.92 28.75,161.29 C6.1@32.46,165 ; R29.1@36.25,167.5 R30.1@40,167.5 ; R29.1@36.25,167.58 35.04,167.58 C6.1@32.5,165.04 C6.1@32.46,165 ; C31.1@37.54,26.25 37.5,26.21 D18.15@37.5,23.75 37.5,20.217 37.719,19.999 ; 59.796,19.999 60,20.203 D22.16@60,23.75 ; 127.5,93.749 D7.2@127.5,96.25
  Bottom Layer, Bottom w1.25: v1(10,38.75) 10,38.999 14.75,43.749 ; D16.1@10,46.25 12.501,43.749 14.75,43.749 ; v1(10,103.75) 40,103.75 D2.16@47.5,96.25 50.001,93.749 57.5,93.749 ; 25,43.749 D16.7@25,46.25 ; D19.8@27.5,16.25 27.5,19.999 ; R16.1@31.33,145 31.33,141.17 35.375,137.125 45.875,137.125 47.5,138.75 R36.2@47.58,138.75 50,141.17 R33.1@52.42,141.17 ; D9.7@47.5,46.25 47.5,43.749 ; v1(50,147.5) 54.96,147.5 ; D18.8@52.5,16.25 52.5,19.996 ; 52.5,93.75 D2.18@52.5,96.25 ; R33.1@52.5,141.17 R33.1@52.42,141.17 ; R33.1@52.5,141.25 R33.1@52.42,141.17 ; 55,93.75 D2.19@55,96.25 ; C7.1@56.25,146.21 54.961,147.499 79.999,147.499 86.25,153.75 ; D2.20@57.5,96.25 57.5,93.749 ; D10.7@70,46.25 70,43.749 ; D6.2@70,96.25 70,93.749 ; C29.2@78.75,47.46 78.75,43.749 ; 85,19.999 D23.16@85,23.75 ; 86.25,154.5 86.25,153.75 ; 88.749,177.499 P1.A1@90,178.75 87.904,177.703 P1.B1@90,176.25 ; D5.7@97.5,46.25 97.5,43.749 ; D6.14@100,96.25 100,93.749 ; D20.7@100,156.25 100,153.894 99.856,153.75 ; 110,19.999 D24.16@110,23.75 ; D11.4@112.5,46.25 112.5,43.749 ; D11.5@115,46.25 115,43.749 ; D11.8@122.5,46.25 122.5,43.749 ; D7.1@125,96.25 125,93.749 ; 135,20.192 D25.16@135,23.75 ; D4.7@145,46.25 145,43.749 ; 148.75,43.749 145,43.749 ; C24.1@148.75,47.46 148.75,43.75 165,43.75 ; D7.12@152.5,96.25 152.5,93.749 ; D14.7@157.5,156.25 157.5,153.75 ; 160,20.192 D26.16@160,23.75 ; D3.6@165,46.25 165,43.75 ; D3.7@167.5,46.25 167.5,43.75 ; D13.2@177.5,46.25 177.5,43.75 ; C13.1@178.75,146.29 178.75,148.75 ; D13.3@180,46.25 180,43.891 179.859,43.75 ; 185,20.192 D27.16@185,23.75 ; D13.7@190,46.25 187.5,43.75 179.859,43.75 ; C11.1@193.75,52.54 194.96,53.75 D1.8@197.5,53.75 199.325,55.575 214.075,55.575 221.275,62.775 232.185,62.775 C2.1@232.5,62.46 235,59.96 R2.1@235,56.25 235,55 C1.2@230,50 ; C16.1@203.79,93.75 203.79,91.249 ; C22.1@206.25,18.79 206.25,20.192 ; 210,20.192 D28.16@210,23.75 ; v1(210,150) 208.75,148.75 ; 231.25,20.192 231.442,20.192 D29.16@235,23.75 ; C12.1@247.46,125 247.5,125.04 D12.12@247.5,136.25 249.125,137.875 249.125,140.673 243.548,146.25 v1(230,146.25) 216.87,146.25 214.37,148.75 208.75,148.75 ; D8.20@247.5,96.25 242.499,91.249 203.79,91.249 ; 14.75,43.749 47.5,43.749 ; 47.5,43.749 70,43.749 ; 57.5,93.749 70,93.749 ; 70,43.749 78.75,43.749 ; 70,93.749 87.5,93.749 91.314,93.749 91.815,94.25 93.265,94.25 93.766,93.749 100,93.749 ; 78.75,43.749 v1(89.997,43.749) 97.5,43.749 ; 86.25,153.75 99.856,153.75 ; 97.5,43.749 112.5,43.749 ; 99.856,153.75 157.5,153.75 ; 100,93.749 125,93.749 ; 112.5,43.749 115,43.749 ; 115,43.749 122.5,43.749 ; 122.5,43.749 145,43.749 ; 125,93.749 127.5,93.749 152.5,93.749 ; 152.5,93.749 191.247,93.749 193.246,91.75 193.747,91.249 203.79,91.249 ; 157.5,153.75 170,153.75 v1(172.5,151.25) 175,148.75 178.75,148.75 ; 165,43.75 167.5,43.75 ; 167.5,43.75 177.5,43.75 ; 177.5,43.75 179.859,43.75 ; 178.75,148.75 208.75,148.75
  Bottom Layer, Bottom w2.5: C10.1@50.96,173.75 50.96,177.499 ; 88.749,177.499 50.96,177.499 ; 231.25,20.192 210,20.192 206.25,20.192 185,20.192 160,20.192 135,20.192 131.25,20.192 131.443,19.999 110,19.999 85,19.999 59.796,19.999 37.719,19.999 27.5,19.999 17.5,19.999 12.61,19.999 7.743,19.999 3.7,24.042 3.7,33.453 3.747,33.5 3.747,159.997 21.249,177.499 50.96,177.499
HLDA: D2.7 D6.21 | length 120.1
  Top Layer, Top w0.4: v1(115,86.25) 116.15,87.4 116.15,110.1 D6.21@115,111.25
  Bottom Layer, Bottom w0.4: D2.7@25,96.25 35,86.25 v1(115,86.25)
HRQ: D2.10 D6.13 | length 78.1
  Top Layer, Top w0.4: v1(97.5,87.5) D6.13@97.5,96.25
  Bottom Layer, Bottom w0.4: D2.10@32.5,96.25 32.5,95 40,87.5 88.383,87.5 88.457,87.574 v1@97.426,87.574
LUMA: D9.10 R15.1 | length 113.2
  Top Layer, Top w0.4: D9.10@42.5,53.75 43.75,55 v1(43.75,67.5)
  Bottom Layer, Bottom w0.4: R15.1@8.67,140 7.55,138.88 7.55,84.959 19.959,72.55 38.7,72.55 v1(43.75,67.5)
MA0: D22.5 D23.5 D24.5 D25.5 D26.5 D27.5 D28.5 D29.5 R21.1 | length 254.3
  Top Layer, Top w0.4: v1(95,6.25) D23.5@95,16.25 ; v1(120,6.25) D24.5@120,16.25 ; v1(145,6.25) D25.5@145,16.25 ; v1(170,6.25) D26.5@170,16.25 ; v1(195,6.25) D27.5@195,16.25 ; v1(220,6.25) D28.5@220,16.25 ; v1(245,6.25) D29.5@245,16.25
  Bottom Layer, Bottom w0.4: D22.5@70,16.25 70,7.5 71.25,6.25 v1(95,6.25) v1(120,6.25) v1(145,6.25) v1(170,6.25) v1(195,6.25) v1(220,6.25) v1(245,6.25)
MA1: D22.7 D23.7 D24.7 D25.7 D26.7 D27.7 D28.7 D29.7 R22.1 | length 233.8
  Top Layer, Top w0.4: v1(100,8.75) D23.7@100,16.25 ; v1(125,8.75) D24.7@125,16.25 ; v1(150,8.75) D25.7@150,16.25 ; v1(175,8.75) D26.7@175,16.25 ; v1(200,8.75) D27.7@200,16.25 ; v1(225,8.75) D28.7@225,16.25 ; v1(250,8.75) D29.7@250,16.25
  Bottom Layer, Bottom w0.4: D22.7@75,16.25 75,11.25 77.5,8.75 v1(100,8.75) v1(125,8.75) v1(150,8.75) v1(175,8.75) v1(200,8.75) v1(225,8.75) 225.274,9.024 249.726,9.024 v1(250,8.75)
MA2: D22.6 D23.6 D24.6 D25.6 D26.6 D27.6 D28.6 D29.6 R23.1 | length 262
  Top Layer, Top w0.4: R23.1@56.25,13.75 72.5,13.75 ; D22.6@72.5,16.25 72.5,13.75 ; D23.6@97.5,16.25 v1(97.5,7.5) 97.5,7.053 92.997,2.55 89.503,2.55 78.303,13.75 72.5,13.75 ; v1(122.5,7.5) D24.6@122.5,16.25 ; v1(147.5,7.5) D25.6@147.5,16.25 ; v1(172.5,7.5) D26.6@172.5,16.25 ; v1(197.5,7.5) D27.6@197.5,16.25 ; v1(222.5,7.5) D28.6@222.5,16.25 ; v1(247.5,7.5) D29.6@247.5,16.25
  Bottom Layer, Bottom w0.4: v1(97.5,7.5) v1(122.5,7.5) v1(147.5,7.5) v1(172.5,7.5) v1(197.5,7.5) v1(222.5,7.5) v1(247.5,7.5)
